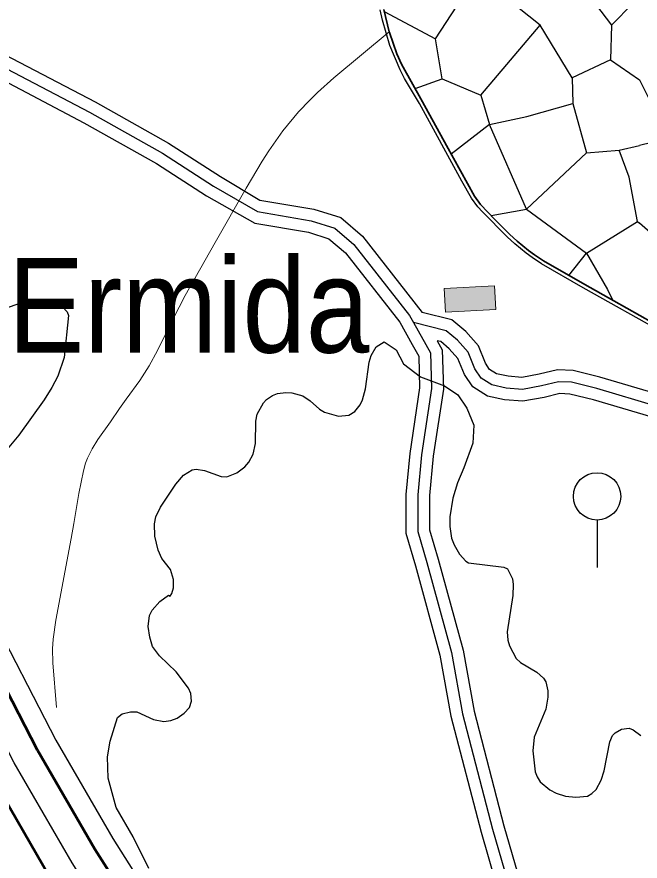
# Model space of a CAD drawing. Extents: x -64005 to -55000, y -89025 to -80000.
# Drawn here: x -57075 to -56548, y -88274 to -87561 of the extents above; entities that cross this region are included whole.
import ezdxf
from ezdxf.enums import TextEntityAlignment as Align

# ---------------------------------------------------------------- set-up
doc = ezdxf.new("R2010")
doc.units = 0
doc.header["$LTSCALE"] = 32
doc.linetypes.add('LONG_DASHED', pattern=[7.5, 6, -1.5])
for name, color, linetype, lineweight in [('1', 7, 'Continuous', 25), ('19', 7, 'Continuous', 25), ('2', 7, 'Continuous', 25), ('24', 7, 'Continuous', 25), ('32', 7, 'Continuous', 25), ('39', 7, 'LONG_DASHED', 25), ('6', 7, 'Continuous', 25), ('7', 7, 'Continuous', 13), ('8', 7, 'Continuous', 25)]:
    doc.layers.add(name, color=color, linetype=linetype, lineweight=lineweight)
doc.layers.add('45', color=7, linetype='Continuous')

msp = doc.modelspace()

# ---------------------------------------------------------------- hatches: boundary and pattern name
at = {"layer": '7'}
msp.add_hatch(color=256, dxfattribs=at).paths.add_polyline_path([(-56671.33, -87787.99), (-56713.77, -87790.15), (-56712.75, -87810.13), (-56670.31, -87807.97)])

# ---------------------------------------------------------------- linework, layer by layer
at = {"layer": '1'}
for points in [[(-57109.64, -87815.52), (-57073.39, -87803.12), (-57063.71, -87800.81), (-57051.22, -87800.12), (-57043.78, -87801.64), (-57036.03, -87805.66), (-57032.1, -87809.97), (-57031.04, -87812.99), (-57034.68, -87848.62), (-57040.04, -87864.29), (-57044.87, -87873.88), (-57051.34, -87884.18), (-57072.74, -87914.06), (-57091.53, -87935.95)], [(-56771.11, -87839.66), (-56764.37, -87835.19), (-56754.19, -87841.98), (-56748.24, -87853.87), (-56733.81, -87864.91), (-56713.44, -87872.56), (-56702.4, -87880.2), (-56694.76, -87891.24), (-56688.82, -87905.68), (-56689.67, -87920.96), (-56697.28, -87941.7)], [(-56963, -88280.15), (-56976.47, -88253.19), (-56990.7, -88228.47), (-56997.44, -88203.75), (-56998.14, -88185.77), (-56995.8, -88172.45), (-56989.44, -88152.59), (-56985.53, -88149.46), (-56978.59, -88147.63), (-56973.15, -88147.77), (-56959.2, -88154.1), (-56950.53, -88155.98), (-56944.6, -88155.2), (-56939.18, -88153.04), (-56933.21, -88149.01), (-56928.83, -88143.99), (-56926.98, -88138.63), (-56927.66, -88132.25), (-56929.75, -88127.7), (-56940.17, -88113.88), (-56954.19, -88100.61), (-56959.97, -88092.61), (-56962.2, -88084.68), (-56963.64, -88075.65), (-56962.51, -88066.47), (-56960.3, -88061.99), (-56953.96, -88054.7), (-56946.43, -88049.35), (-56945.13, -88050), (-56943.57, -88047.76), (-56942.26, -88042.96), (-56942.35, -88036.04), (-56944.87, -88027.58), (-56952.03, -88018.19), (-56955.3, -88011.25), (-56958.15, -87999.5), (-56958.41, -87989.04), (-56957.18, -87983), (-56953.2, -87974.91), (-56940.26, -87955.38), (-56933.83, -87947.95), (-56926.49, -87943.5), (-56923.16, -87942.82), (-56916.23, -87944.01), (-56901.98, -87949.09), (-56897.34, -87949.26), (-56888.91, -87945.89), (-56882.12, -87940.81), (-56878.64, -87936.87), (-56874.92, -87930.26), (-56873.12, -87921.03), (-56872.83, -87902.19), (-56871.6, -87896.26), (-56866.44, -87886.88), (-56863.65, -87883.92), (-56858.68, -87880.54), (-56854.39, -87878.96), (-56847.33, -87878.09), (-56842.48, -87878.41), (-56833.15, -87880.92), (-56826.82, -87885.1), (-56819.13, -87892.05), (-56814.77, -87894.73), (-56802.88, -87898.01), (-56794.2, -87897.31), (-56789.22, -87894.08), (-56784.73, -87888.44), (-56782.66, -87884.19), (-56780.15, -87874.92), (-56777.08, -87852.55), (-56775.44, -87846.86), (-56771.11, -87839.66)], [(-56697.28, -87941.7), (-56702.43, -87954.25), (-56706.46, -87967.28), (-56709.12, -87983.18), (-56709.14, -87991.33), (-56707.48, -88001.08), (-56705.49, -88006.63), (-56700.91, -88014.48), (-56695.5, -88020.51), (-56693.12, -88021.99), (-56663.31, -88025.59), (-56660.21, -88027.06), (-56656.16, -88035.46), (-56655.5, -88040.12), (-56655.75, -88049.45), (-56660.7, -88080.34), (-56660.05, -88087.25), (-56658.68, -88091.93), (-56653.02, -88102.75), (-56649.34, -88106.23), (-56635.54, -88114.33), (-56629.85, -88119.25), (-56627.97, -88122.44), (-56626.2, -88130.02), (-56626.16, -88135.34), (-56627.98, -88145.64), (-56637.89, -88169.24), (-56638.94, -88180.62), (-56636.87, -88198.55), (-56635.35, -88202.71), (-56632.71, -88206.76), (-56624.53, -88213.72), (-56619.36, -88216.5), (-56611.51, -88218.98), (-56602.78, -88219.85), (-56592.81, -88218.92), (-56589, -88216.8), (-56585.57, -88213.24), (-56581.31, -88205.33), (-56578.8, -88197.45), (-56574.01, -88173.11), (-56571.63, -88167.83), (-56569.32, -88165.45), (-56564.15, -88162.45), (-56557.59, -88161.65), (-56554.17, -88162.9), (-56547.87, -88167.81)]]:
    msp.add_lwpolyline(points, dxfattribs=at)
at = {"layer": '19'}
for p, q in [((-56675.4, -87651.81), (-56707.81, -87676.94)), ((-56644.34, -87723.32), (-56593.73, -87675.8)), ((-56608.44, -87779.25), (-56593.6, -87760.36))]:
    msp.add_line(p, q, dxfattribs=at)
for points in [[(-56764.46, -87556.28), (-56721.14, -87579.46), (-56694.07, -87537.71), (-56714.5, -87518.73)], [(-56604.84, -87525.24), (-56572.44, -87567.89), (-56554.24, -87549.23), (-56548.89, -87518.73)], [(-56760.24, -87573.57), (-56764.87, -87554.6)], [(-56715.38, -87613.19), (-56682.95, -87626.95), (-56632.8, -87567.88), (-56651.9, -87552.78)], [(-56573.3, -87597.19), (-56605.72, -87612.29), (-56632.8, -87567.88)], [(-56572.44, -87567.89), (-56573.3, -87597.19), (-56548.89, -87614.15)], [(-56476.61, -87863.36), (-56486.63, -87852.07), (-56494.33, -87843.84), (-56498.8, -87840.46), (-56526.55, -87825.46), (-56570.7, -87800.56), (-56595.04, -87786.98), (-56629.86, -87766.88), (-56637.65, -87761.8), (-56642.63, -87758.11), (-56652.22, -87750.18), (-56658.64, -87744.33), (-56670.9, -87732.06), (-56683.09, -87719.36), (-56688.17, -87712.25), (-56711.94, -87669.51), (-56732.04, -87632.72), (-56749.87, -87600.73), (-56753.85, -87592.11), (-56760.06, -87574.13), (-56760.24, -87573.57)], [(-56738.37, -87621.36), (-56715.38, -87613.19), (-56721.14, -87579.46)], [(-56605.72, -87612.29), (-56605.27, -87634.05), (-56593.73, -87675.8), (-56566.2, -87673.58), (-56548.89, -87669.43)], [(-56548.89, -87614.15), (-56536.28, -87639.41), (-56538.5, -87666.93), (-56548.89, -87669.43)], [(-56682.95, -87626.95), (-56675.4, -87651.81), (-56643.89, -87645.16), (-56605.27, -87634.05)], [(-56674.2, -87728.62), (-56644.34, -87723.32), (-56675.4, -87651.81)], [(-56550.54, -87733.7), (-56557.65, -87696.39), (-56566.2, -87673.58)], [(-56644.34, -87723.32), (-56593.6, -87760.36), (-56550.54, -87733.7), (-56548.89, -87735.17)], [(-56443.06, -87776.2), (-56467.46, -87793.07), (-56488.78, -87795.72), (-56510.08, -87789.51), (-56515.41, -87754.87), (-56537.6, -87745.1), (-56548.89, -87735.17)], [(-56593.6, -87760.36), (-56575.85, -87791), (-56571.74, -87799.98)]]:
    msp.add_lwpolyline(points, dxfattribs=at)
at = {"layer": '2', "lineweight": 13}
msp.add_lwpolyline([(-56760.24, -87573.56), (-56806.92, -87612.45), (-56820.64, -87624.66), (-56827.21, -87631.11), (-56836.68, -87641.2), (-56849.93, -87657.17), (-56861.94, -87674.06), (-56867.44, -87682.82), (-56880.92, -87705.56), (-56907.19, -87751.37), (-56932.34, -87796.22), (-56942.65, -87815.98), (-56955.91, -87842.58), (-56962.97, -87855.65), (-56970.82, -87867.93), (-56982.22, -87883.72), (-56987.76, -87891.75), (-56995.6, -87902.94), (-57006.16, -87917.89), (-57010.88, -87925.61), (-57014.87, -87933.64), (-57016.5, -87937.8), (-57018.39, -87944.26), (-57022.2, -87963.29), (-57026.38, -87988.77), (-57028.6, -88001.49), (-57041.73, -88070.4), (-57043.89, -88086.42), (-57044.39, -88094.46), (-57044.28, -88106.5), (-57041.16, -88144.18)], dxfattribs=at)
at = {"layer": '2'}
msp.add_lwpolyline([(-56823.95, -88561.02), (-56842.46, -88539.59), (-56897.81, -88467), (-56974, -88360.46), (-57027.84, -88275.35), (-57076.74, -88190.8), (-57135.5, -88077.06), (-57179.86, -87979.43), (-57231.44, -87844.28), (-57264.04, -87743.8), (-57291.34, -87650.15), (-57305.9, -87585.96)], dxfattribs=at)
at = {"layer": '2', "lineweight": 53}
for points in [[(-56807.88, -88545.21), (-56824.98, -88525.4), (-56879.71, -88453.63), (-56955.33, -88347.89), (-57008.59, -88263.7), (-57057, -88180), (-57115.25, -88067.24), (-57159.09, -87970.76), (-57210.21, -87836.79), (-57242.53, -87737.18), (-57269.55, -87644.51), (-57283.96, -87580.97)], [(-56840.02, -88576.84), (-56859.94, -88553.78), (-56915.91, -88480.37), (-56992.67, -88373.03), (-57047.09, -88287), (-57096.48, -88201.6), (-57155.75, -88086.88), (-57200.63, -87988.1), (-57252.67, -87851.77), (-57285.55, -87750.42), (-57313.13, -87655.79), (-57327.87, -87590.81)]]:
    msp.add_lwpolyline(points, dxfattribs=at)
at = {"layer": '24'}
for points in [[(-57151.17, -86431.13), (-57212.84, -86444.47), (-57224.62, -86491.63), (-57243.36, -86570.34), (-57265.93, -86581.07), (-57294.82, -86727.75), (-57310.07, -86850.29), (-57317.5, -86939.54), (-57322.34, -87045.7), (-57323.06, -87147.4), (-57315.23, -87253.55), (-57307.36, -87342.34), (-57293.22, -87444.99), (-57273.81, -87546.62), (-57252.6, -87640.12), (-57225.81, -87732.03), (-57193.71, -87830.97), (-57142.93, -87964.01), (-57099.5, -88059.6), (-57041.64, -88171.6), (-56993.61, -88254.64), (-56940.8, -88338.12), (-56865.63, -88443.23), (-56826.11, -88493.67)], [(-56506.6, -87839.45), (-56528, -87828.09), (-56596.52, -87789.59), (-56631.51, -87769.39), (-56639.4, -87764.24), (-56644.45, -87760.5), (-56654.17, -87752.47), (-56660.67, -87746.55), (-56681.49, -87725.62), (-56685.48, -87721.21), (-56690.64, -87713.98), (-56698.76, -87699.71), (-56734.67, -87634.17), (-56747.15, -87612.98), (-56750.92, -87605.73), (-56759.63, -87585.14), (-56765.97, -87563.63), (-56767.85, -87555.08)]]:
    msp.add_lwpolyline(points, dxfattribs=at)
at = {"layer": '32'}
msp.add_line((-56584.75, -87985.8), (-56584.75, -88025.8), dxfattribs=at)
msp.add_circle((-56584.75, -87965.8), 20, dxfattribs=at)
at = {"layer": '39'}
for points in [[(-57089.3, -87601.56), (-57013.13, -87641.48), (-56951.57, -87676.12), (-56908.46, -87703.84), (-56871.52, -87725.39), (-56826.11, -87733.09), (-56806.1, -87739.25), (-56789.94, -87753.11), (-56742.99, -87813.16), (-56739.67, -87819.08)], [(-56739.67, -87819.08), (-56725.29, -87844.73), (-56724.51, -87874.77), (-56732.98, -87930.74), (-56736.06, -87964.62), (-56736.06, -87995.43), (-56728.36, -88021.61), (-56707.58, -88097.75), (-56698.35, -88149.33), (-56672.98, -88246.8), (-56649.89, -88326.1), (-56627.48, -88410.55)], [(-56520.55, -87898.81), (-56534.02, -87889.83), (-56585.04, -87874.71), (-56606.21, -87869.42), (-56617.17, -87869.04), (-56631.53, -87872.45), (-56647.78, -87875.48), (-56661.39, -87874.34), (-56673.48, -87871.7), (-56682.56, -87866.05), (-56687.85, -87858.11), (-56693.52, -87844.13), (-56702.61, -87833.92), (-56712.05, -87825.98), (-56739.67, -87819.08)]]:
    msp.add_lwpolyline(points, dxfattribs=at)
at = {"layer": '6', "lineweight": 35}
for points in [[(-56760.24, -87573.56), (-56764.87, -87554.6)], [(-56760.24, -87573.56), (-56760.06, -87574.13), (-56753.85, -87592.11), (-56749.87, -87600.73), (-56732.04, -87632.72), (-56711.94, -87669.51), (-56688.17, -87712.25), (-56683.09, -87719.36), (-56670.9, -87732.06), (-56658.64, -87744.33), (-56652.22, -87750.18), (-56642.63, -87758.11), (-56637.65, -87761.8), (-56629.86, -87766.88), (-56595.04, -87786.98), (-56570.7, -87800.56), (-56526.55, -87825.46)]]:
    msp.add_lwpolyline(points, dxfattribs=at)
at = {"layer": '7'}
msp.add_lwpolyline([(-56671.33, -87787.99), (-56713.77, -87790.15), (-56712.75, -87810.13), (-56670.31, -87807.97)], close=True, dxfattribs=at)
at = {"layer": '8'}
for points in [[(-57084.9, -87592.58), (-57008.35, -87632.69), (-56946.41, -87667.55), (-56902.58, -87695.73), (-56869.3, -87715.62), (-56823.79, -87723.34), (-56801.17, -87730.3), (-56782.67, -87746.17), (-56732.28, -87810.62)], [(-56719.63, -87834.39), (-56715.36, -87842), (-56714.49, -87875.39), (-56723.05, -87931.94), (-56726.06, -87965.07), (-56726.06, -87993.98), (-56718.74, -88018.87), (-56697.82, -88095.55), (-56688.57, -88147.19), (-56663.34, -88244.14), (-56640.26, -88323.42), (-56620.4, -88398.23)], [(-56522.06, -87909.82), (-56538.31, -87899), (-56587.67, -87884.36), (-56607.61, -87879.38), (-56616.17, -87879.08), (-56629.46, -87882.24), (-56647.27, -87885.56), (-56662.88, -87884.25), (-56677.3, -87881.1), (-56689.68, -87873.4), (-56696.75, -87862.81), (-56702.15, -87849.49), (-56709.6, -87841.11), (-56716.72, -87835.12), (-56719.63, -87834.39)]]:
    msp.add_lwpolyline(points, dxfattribs=at)
at = {"layer": '8', "linetype": 'LONG_DASHED'}
for points in [[(-57093.7, -87610.54), (-57017.91, -87650.27), (-56956.73, -87684.69), (-56914.35, -87711.95), (-56873.74, -87735.17), (-56828.43, -87742.84), (-56811.03, -87748.2), (-56797.21, -87760.05), (-56751.34, -87818.73), (-56740.7, -87837.69)], [(-56516.88, -87889.23), (-56529.73, -87880.67), (-56582.41, -87865.06), (-56604.81, -87859.46), (-56618.17, -87859), (-56633.6, -87862.65), (-56648.29, -87865.4), (-56659.9, -87864.43), (-56669.66, -87862.3), (-56675.44, -87858.7), (-56678.96, -87853.41), (-56684.9, -87838.77), (-56695.61, -87826.73), (-56707.38, -87816.84), (-56732.28, -87810.62)], [(-56740.7, -87837.69), (-56735.22, -87847.47), (-56734.53, -87874.15), (-56742.91, -87929.54), (-56746.06, -87964.17), (-56746.06, -87996.87), (-56737.98, -88024.34), (-56717.34, -88099.95), (-56708.13, -88151.47), (-56682.62, -88249.46), (-56659.52, -88328.79), (-56639.41, -88404.6)]]:
    msp.add_lwpolyline(points, dxfattribs=at)

# ---------------------------------------------------------------- texts
at = {"layer": '45', "width": 0.9}
msp.add_text('Ermida', height=80, rotation=0.007, dxfattribs=at).set_placement((-56929.43, -87844.43), align=Align.CENTER)

doc.saveas('drawing.dxf')
